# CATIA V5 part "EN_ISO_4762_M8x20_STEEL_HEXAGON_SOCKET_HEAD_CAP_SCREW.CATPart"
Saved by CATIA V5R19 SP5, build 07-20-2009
Part number: EN ISO 4762 SCREW M8x20 STEEL HEXAGON SOCKET HEAD CAP
Publications: "Mating Face", "Axis"
Bounding box of the stored display mesh (mm): x -20 to 8, y -6.5 to 6.5, z -6.337 to 6.337
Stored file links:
  Z:\UA\ATLAS\atlascar\ServoPiloto\dir\suportePotenciometro\V2\EN_ISO_4762_M8x20_STEEL_HEXAGON_SOCKET_HEAD_CAP_SCREW.CATPart
  Z:\programs_vbox\Dassault Systemes\B19\intel_a\startup\components\MechanicalStandardParts\EN_Standards\Design_Tables\EN_ISO_4762_HEXAGON_SOCKET_HEAD_CAP_SCREW.txt
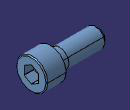
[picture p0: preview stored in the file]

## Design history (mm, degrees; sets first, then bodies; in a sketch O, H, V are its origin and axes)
Parameters
  d_dia = 8 mm
  l_nom = 20 mm
  k_head_depth_max = 8 mm
  s_nom = 6 mm
  r_min = 0.4 mm
  ds_max = 8 mm
  e = 6.863 mm
  t_min = 4 mm
  p_pitch = 1.25 mm
  Threading = 16.25 mm
  dk_max = 13 mm
Body1 "PartBody" (main body)
  Sketch1 on yz-plane, origin (0, 0, 0), H (0, 1, 0), V (0, 0, 1)
    circle A1 centre (0, 0) radius 6.5
    radius A1 = 6.5 {= dk_max /2}
  Pad1: profile Sketch1, direction (1, 0, 0), length 8 {= k_head_depth_max}
  Fillet1: radius 0.4 {= r_min}, on edge [face of Pad1 | face of Pad1]
  Body2
    Sketch2 on face of Pad1, origin (8, 0, 0), H (0, 1, 0), V (0, 0, 1)
      point P1 (3, -1.7321)
      point P2 (3, 1.7321)
      point P3 (0, 3.4641)
      point P4 (-3, 1.7321)
      point P5 (-3, -1.7321)
      point P6 (0, -3.4641)
      point P7 (3, 0)
      line L1 (3, -1.7321) -> (3, 1.7321)
      line L2 (3, 1.7321) -> (0, 3.4641)
      line L3 (0, 3.4641) -> (-3, 1.7321)
      line L4 (-3, 1.7321) -> (-3, -1.7321)
      line L5 (-3, -1.7321) -> (0, -3.4641)
      line L6 (0, -3.4641) -> (3, -1.7321)
      construction line L7 (0, 0) -> (3, 0)
      construction circle A1 centre (0, 0) radius 3.4641
      construction arc A2 centre (-3, -1.7321) radius 3.4641 from (-3, 1.7321) to (0, -3.4641) cw
      construction arc A3 centre (3, 1.7321) radius 3.4641 from (0, 3.4641) to (3, -1.7321) ccw
      point P8 (-3, -1.7321)
      point P9 (3, 1.7321)
      distance L1 L4 = 6 {= s_nom}
      horizontal: L7 H
      coincidence: A1 P1, A1 P2, A1 P3, A1 P4, A1 P5, A1 P6, A2 P4, A2 P6, A2 O, P8 P5, A3 P3, A3 P1, A3 O, P9 P2
      midpoint: P7 L1
    Pad2: profile Sketch2, direction (-1, 0, 0), length 5.9778 {= t_min +(e /3.47)}
    Body3
      Sketch3 on zx-plane, origin (0, 0, 0), H (-1, 0, 0), V (0, 0, 1)
        point P1 (-2.0188, 0)
        line L1 (-2.0188, 0) -> (-4, 3.4315)
        line L2 (-4, 3.4315) -> (-8, 3.4315)
        line L3 (-8, 3.4315) -> (-8, 0)
        axis line L4 (-46.2384, 0) -> (26.3409, 0)
        reference projected line E1 (-8, -6.9227) -> (-8, 6.9227) from edge [face of Pad2 | face of Pad2]
        length L2 = 4 {= t_min}
        angle L1 L4 = 60
        distance L2 L4 = 3.4315 {= e /2}
        horizontal: L2 H, L4 H
        perpendicularity: L3 L2
        fix: L4
        coincidence: L3 E1, P1 L4
      Shaft1: profile Sketch3, axis Sketch3.L4, angle 360
    Intersect1: tool Body3
  Remove1: tool Body2
  Sketch4 on xy-plane, origin (0, 0, 0), H (1, 0, 0), V (0, 1, 0)
    line L1 (0, 0) -> (0, 4)
    line L2 (0, 4) -> (-3.75, 4)
    line L3 (-3.75, 4) -> (-3.75, 3.9024)
    line L4 (-3.75, 3.9024) -> (-20, 3.9024)
    line L5 (-20, 3.9024) -> (-20, 0)
    axis line L6 (-192.3446, 0) -> (99.1594, 0)
    distance L5 L1 = 20 {= l_nom}
    distance L3 L5 = 16.25 {= Threading}
    distance L2 L6 = 4 {= ds_max /2}
    distance L4 L6 = 3.9024 {= d_dia /2.05}
    vertical: L1 V, L3 V, L5 V
    horizontal: L2 H, L4 H, L6 H
    fix: L6
  Shaft2: profile Sketch4, axis Sketch4.L6, angle 360
  Fillet2: radius 0.4 {= r_min}, on edge [face of Shaft2 | face of Pad1]
  Chamfer1: length 1.25 {= p_pitch}, angle 45, on edge [face of Shaft2 | face of Shaft2]
  Thread1: diameter 7.8049 {= d_dia /1.025}, depth 16.25 {= Threading}, pitch 1, on face of Shaft2, from face of Shaft2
